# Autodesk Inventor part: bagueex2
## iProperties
Created: 2006-05
Part Number: bagueex2
Document SubType Name: Modeling
Designer: Administrateur
Manufacturer: Standard
Standards Organization: Custom
Author: Administrateur
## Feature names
1. Extrusion1
2. Extrusion2
